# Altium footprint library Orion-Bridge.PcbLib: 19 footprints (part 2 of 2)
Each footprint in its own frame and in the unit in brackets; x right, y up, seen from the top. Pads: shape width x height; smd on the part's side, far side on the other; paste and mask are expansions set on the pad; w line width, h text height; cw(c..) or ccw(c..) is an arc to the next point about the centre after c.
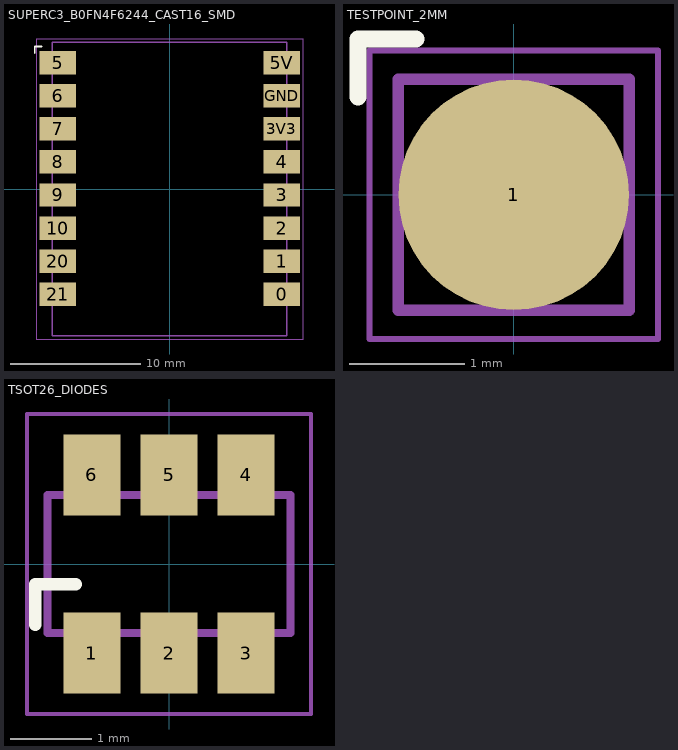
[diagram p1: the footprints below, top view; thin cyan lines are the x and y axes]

## SUPERC3_B0FN4F6244_CAST16_SMD [mm] "Selected ASIN B0FN4F6244. 16 SMD lands only, 2.8x1.8 at X +/-8.6; 2.54 pitch from Nologo reference. Outer castellation dimensions inferred from selected product photo, not a manufacturer land drawing. Manual perimeter soldering; no stencil paste, no carrier PTH, no pin headers. USB tails require the separate carrier cutout; see mechanical_interfaces."
height 4.4
pads (16):
  rect 2.8x1.8 smd paste-10: 0(8.6,-8.079) 1(8.6,-5.539) 2(8.6,-2.999) 3(8.6,-0.459) 3V3(8.6,4.621) 4(8.6,2.081) 5(-8.6,9.701) 5V(8.6,9.701) 6(-8.6,7.161) 7(-8.6,4.621) 8(-8.6,2.081) 9(-8.6,-0.459) 10(-8.6,-2.999) 20(-8.6,-5.539) 21(-8.6,-8.079) GND(8.6,7.161)
Top Overlay:
  lines w0.15: -10.35,10.451 -10.35,10.951 -9.85,10.951
Component bodies:
  lines w0.1: -9,-11.26 9,-11.26 9,11.26 -9,11.26 -9,-11.26
Courtyards:
  lines w0.05: -10.25,-11.51 10.25,-11.51 10.25,11.51 -10.25,11.51 -10.25,-11.51
3D body: height 1.1, standoff 0.1, extent -9,-11.26 9,11.26
3D body: height 2.05, standoff 1.1, extent -2.886,-6.986 4.186,0.086
3D body: height 2.35, standoff 1.1, extent -3.5,-11.1 3.5,-8.8
3D body: height 2.4, standoff 2.35, extent -3.025,-11.09 3.025,-8.81
3D body: height 1.9, standoff 1.1, extent -6.1,-8.5 -2.9,-6
3D body: height 2.2, standoff 1.1, extent -6.9,-1.3 -4,0.3
3D body: height 1.32, standoff 1.1, extent -4.6,4.65 4.6,12.65
3D body: height 4.4, standoff 4.18, extent -4.6,4.65 4.6,12.65
3D body: height 4.18, standoff 1.32, extent -4.6,4.65 -4.4,12.65
3D body: height 4.18, standoff 1.32, extent 4.4,4.65 4.6,12.65
3D body: height 4.18, standoff 1.32, extent -4.4,4.65 4.4,5.45
3D body: height 2.91, standoff 2.59, extent -3.35,6.55 3.35,12.35
3D body: height 2.93, standoff 2.91, extent -2.86,8.15 -2.64,11.95
3D body: height 2.93, standoff 2.91, extent -2.36,8.15 -2.14,11.95
3D body: height 2.93, standoff 2.91, extent -1.86,8.15 -1.64,11.95
3D body: height 2.93, standoff 2.91, extent -1.36,8.15 -1.14,11.95
3D body: height 2.93, standoff 2.91, extent -0.86,8.15 -0.64,11.95
3D body: height 2.93, standoff 2.91, extent -0.36,8.15 -0.14,11.95
3D body: height 2.93, standoff 2.91, extent 0.14,8.15 0.36,11.95
3D body: height 2.93, standoff 2.91, extent 0.64,8.15 0.86,11.95
3D body: height 2.93, standoff 2.91, extent 1.14,8.15 1.36,11.95
3D body: height 2.93, standoff 2.91, extent 1.64,8.15 1.86,11.95
3D body: height 2.93, standoff 2.91, extent 2.14,8.15 2.36,11.95
3D body: height 2.93, standoff 2.91, extent 2.64,8.15 2.86,11.95
3D body: height 1.4, standoff -0.65, extent -4.675,5.3 -4.225,6.3
3D body: height 1.4, standoff -0.65, extent -4.675,9.65 -4.225,10.65
3D body: height 1.4, standoff -0.65, extent 4.225,5.3 4.675,6.3
3D body: height 1.4, standoff -0.65, extent 4.225,9.65 4.675,10.65
3D body: height 1.65, standoff 1.1, extent -4.9,0.55 -0.6,4.05
3D body: height 2.15, standoff 1.65, extent -4.8,0.65 -0.7,3.95
3D body: height 2.75, standoff 2.15, extent -3.6,1.45 -1.9,3.15
3D body: height 1.65, standoff 1.1, extent 0.6,0.55 4.9,4.05
3D body: height 2.15, standoff 1.65, extent 0.7,0.65 4.8,3.95
3D body: height 2.75, standoff 2.15, extent 1.9,1.45 3.6,3.15
3D body: height 1.12, standoff 0.08, extent -9,8.926 -8.76,10.476
3D body: height 1.12, standoff 1.1, extent -9,8.926 -7.3,10.476
3D body: height 1.12, standoff 0.08, extent -9,6.386 -8.76,7.936
3D body: height 1.12, standoff 1.1, extent -9,6.386 -7.3,7.936
3D body: height 1.12, standoff 0.08, extent -9,3.846 -8.76,5.396
3D body: height 1.12, standoff 1.1, extent -9,3.846 -7.3,5.396
3D body: height 1.12, standoff 0.08, extent -9,1.306 -8.76,2.856
3D body: height 1.12, standoff 1.1, extent -9,1.306 -7.3,2.856
3D body: height 1.12, standoff 0.08, extent -9,-1.234 -8.76,0.316
3D body: height 1.12, standoff 1.1, extent -9,-1.234 -7.3,0.316
3D body: height 1.12, standoff 0.08, extent -9,-3.774 -8.76,-2.224
3D body: height 1.12, standoff 1.1, extent -9,-3.774 -7.3,-2.224
3D body: height 1.12, standoff 0.08, extent -9,-6.314 -8.76,-4.764
3D body: height 1.12, standoff 1.1, extent -9,-6.314 -7.3,-4.764
3D body: height 1.12, standoff 0.08, extent -9,-8.854 -8.76,-7.304
3D body: height 1.12, standoff 1.1, extent -9,-8.854 -7.3,-7.304
3D body: height 1.12, standoff 0.08, extent 8.76,8.926 9,10.476
3D body: height 1.12, standoff 1.1, extent 7.3,8.926 9,10.476
3D body: height 1.12, standoff 0.08, extent 8.76,6.386 9,7.936
3D body: height 1.12, standoff 1.1, extent 7.3,6.386 9,7.936
3D body: height 1.12, standoff 0.08, extent 8.76,3.846 9,5.396
3D body: height 1.12, standoff 1.1, extent 7.3,3.846 9,5.396
3D body: height 1.12, standoff 0.08, extent 8.76,1.306 9,2.856
3D body: height 1.12, standoff 1.1, extent 7.3,1.306 9,2.856
3D body: height 1.12, standoff 0.08, extent 8.76,-1.234 9,0.316
3D body: height 1.12, standoff 1.1, extent 7.3,-1.234 9,0.316
3D body: height 1.12, standoff 0.08, extent 8.76,-3.774 9,-2.224
3D body: height 1.12, standoff 1.1, extent 7.3,-3.774 9,-2.224
3D body: height 1.12, standoff 0.08, extent 8.76,-6.314 9,-4.764
3D body: height 1.12, standoff 1.1, extent 7.3,-6.314 9,-4.764
3D body: height 1.12, standoff 0.08, extent 8.76,-8.854 9,-7.304
3D body: height 1.12, standoff 1.1, extent 7.3,-8.854 9,-7.304

## TESTPOINT_2MM [mm] "2 mm exposed top-copper test pad; no paste"
pads (1):
  round 2 smd: 1(0,0)
Top Overlay:
  lines w0.15: -1.35,0.85 -1.35,1.35 -0.85,1.35
Component bodies:
  lines w0.1: -1,-1 1,-1 1,1 -1,1 -1,-1
Courtyards:
  lines w0.05: -1.25,-1.25 1.25,-1.25 1.25,1.25 -1.25,1.25 -1.25,-1.25
3D body: height 0.06, standoff 0.03, extent -1,-1 1,1

## TSOT26_DIODES [mm] "Diodes DS41326 Rev3-2 p17 suggested TSOT26 copper: X=.70,Y=1.00,Y1=3.20 total span,C=.95. Top view: pin1 lower-left; pin4 upper-right."
height 1
pads (6):
  rect 0.7x1 smd: 1(-0.95,-1.1) 2(0,-1.1) 3(0.95,-1.1) 4(0.95,1.1) 5(0,1.1) 6(-0.95,1.1)
Top Overlay:
  lines w0.15: -1.65,-0.75 -1.65,-0.25 -1.15,-0.25
Component bodies:
  lines w0.1: -1.5,-0.85 1.5,-0.85 1.5,0.85 -1.5,0.85 -1.5,-0.85
Courtyards:
  lines w0.05: -1.75,-1.85 1.75,-1.85 1.75,1.85 -1.75,1.85 -1.75,-1.85
3D body: height 1, standoff 0.08, extent -1.5,-0.85 1.5,0.85
3D body: height 0.22, standoff 0.03, extent -1.175,-1.35 -0.725,-0.55
3D body: height 0.22, standoff 0.03, extent -0.225,-1.35 0.225,-0.55
3D body: height 0.22, standoff 0.03, extent 0.725,-1.35 1.175,-0.55
3D body: height 0.22, standoff 0.03, extent 0.725,0.55 1.175,1.35
3D body: height 0.22, standoff 0.03, extent -0.225,0.55 0.225,1.35
3D body: height 0.22, standoff 0.03, extent -1.175,0.55 -0.725,1.35
3D body: height 1.01, standoff 1, extent -1.03,-0.64 -0.77,-0.38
